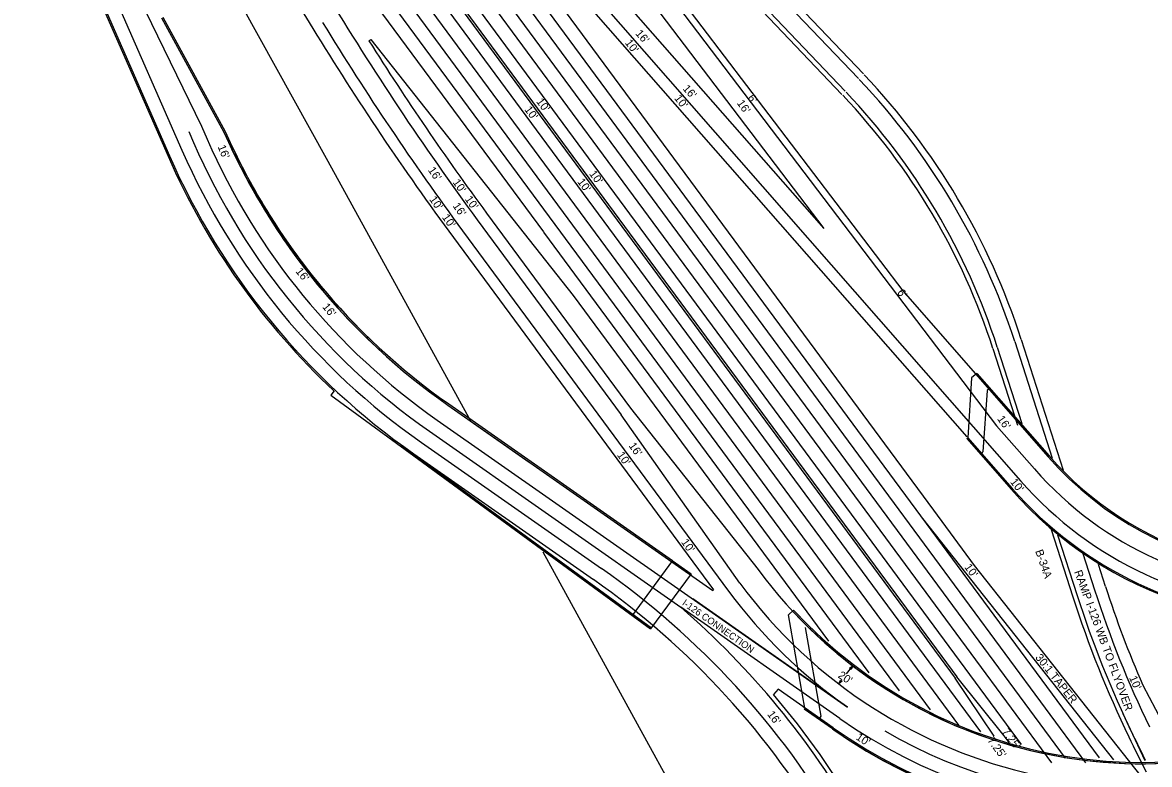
# Model space of a CAD drawing. Extents: x -5665 to 1997148, y 4 to 812485.
# Drawn here: x 1970231 to 1971217, y 796097 to 796747 of the extents above; entities that cross this region are included whole.
import ezdxf

# ---------------------------------------------------------------- set-up
doc = ezdxf.new("R2010")
doc.units = 0
for name, color, linetype in [('BR_CONCRETE', 7, 'Continuous'), ('RD_EX_RailRoad', 7, 'Continuous'), ('RD_PD_ALT1_TrvlWay', 7, 'Continuous'), ('RD_PD_Final_LnLine', 7, 'Continuous'), ('RD_PD_FOC', 7, 'Continuous'), ('RD_PD_MedBWall', 7, 'Continuous'), ('RD_PD_PaveShd', 7, 'Continuous'), ('RD_SHT_TX', 7, 'Continuous')]:
    doc.layers.add(name, color=color, linetype=linetype)

msp = doc.modelspace()

# ---------------------------------------------------------------- linework, layer by layer
at = {"layer": 'BR_CONCRETE'}
for p, q in [((1970278.85, 796811.38), (1970358.4, 796629.63)), ((1970280.04, 796811.9), (1970359.59, 796630.15)), ((1970352.74, 796750.86), (1970407.29, 796650.86)), ((1970353.88, 796751.48), (1970408.44, 796651.48)), ((1971061.08, 796435.65), (1971057.61, 796383.26)), ((1971065.6, 796439.6), (1971061.08, 796435.65)), ((1971064.75, 796438.86), (1971128.01, 796366.63)), ((1971065.6, 796439.6), (1971128.86, 796367.37)), ((1970503.59, 796424.4), (1970500.86, 796420.68)), ((1971074.53, 796424.66), (1971070.98, 796371.04)), ((1971076.88, 796426.72), (1971074.53, 796424.66)), ((1970500.86, 796420.68), (1970780.35, 796216.05)), ((1970603.04, 796411.88), (1970834.74, 796249.56)), ((1970603.79, 796412.95), (1970799.42, 796275.9)), ((1970562.6, 796376.87), (1970781.01, 796216.96)), ((1971056.77, 796382.52), (1971057.61, 796383.26)), ((1971056.77, 796382.52), (1971095.57, 796338.22)), ((1971057.71, 796383.15), (1971096.42, 796338.96)), ((1971068.63, 796368.98), (1971070.98, 796371.04)), ((1970799.42, 796275.9), (1970764.24, 796227.85)), ((1970799.34, 796275.79), (1970815.7, 796264.33)), ((1970815.7, 796264.33), (1970780.35, 796216.05)), ((1970905.37, 796232.3), (1970900.97, 796228.22)), ((1970915.33, 796146.71), (1970900.97, 796228.22)), ((1970929.42, 796139.56), (1970915.76, 796217.11)), ((1970939.35, 796128.51), (1970914.68, 796145.79)), ((1970927.41, 796136.87), (1970929.42, 796139.56))]:
    msp.add_line(p, q, dxfattribs=at)
for centre, radius, start, end in [((1970931.23, 796880.36), 572, 203.65523, 234.98689), ((1970931.23, 796880.36), 570.7, 203.65523, 226.21747), ((1970931.23, 796880.36), 570.7, 203.65523, 234.98689), ((1970931.23, 796880.36), 572, 204.69023, 226.09408), ((1970931.23, 796880.36), 625.3, 203.63926, 226.83775), ((1970931.23, 796880.36), 624, 203.63926, 234.98689), ((1971352.19, 796562.97), 296.88, 221.21202, 283.84721), ((1971352.19, 796562.97), 341.12, 221.21202, 283.34585), ((1971352.19, 796562.97), 340, 221.21202, 314.87827), ((1971210.82, 796516.01), 418, 222.88665, 298.92325), ((1971210.82, 796516.01), 416.88, 222.88665, 298.92325), ((1971210.82, 796516.01), 473.13, 234.98689, 298.92325), ((1971210.82, 796516.01), 472, 234.98689, 298.92325), ((1971210.82, 796516.01), 473.3, 235.20921, 298.92325)]:
    msp.add_arc(centre, radius, start, end, dxfattribs=at)
at = {"layer": 'RD_EX_RailRoad'}
for points in [[(1970394.16, 796813.47), (1970496.54, 796627.92), (1970507.6, 796607.79), (1970622.93, 796398.12)], [(1970685.98, 796283.41), (1970768.64, 796132.97), (1970840.22, 796002.22)]]:
    msp.add_lwpolyline(points, dxfattribs=at)
at = {"layer": 'RD_PD_ALT1_TrvlWay'}
for p, q in [((1970231.16, 797299.2), (1971104.27, 796114.85)), ((1970295.08, 797293.39), (1971172.59, 796103.07)), ((1970542.11, 797011.33), (1970931.78, 796566.41)), ((1970530.07, 797000.79), (1971103.94, 796345.55)), ((1970477.72, 796927.67), (1971068.8, 796125.89)), ((1970439.11, 796899.16), (1970686.58, 796563.47)), ((1970962.1, 796697.61), (1970802.6, 796865.16)), ((1970294.05, 796849.07), (1970387.55, 796656.07)), ((1970950.51, 796686.58), (1970791.01, 796854.13)), ((1970291.03, 796816.71), (1970370.59, 796634.96)), ((1970763.61, 796814.32), (1971082.9, 796393.86)), ((1970750.87, 796804.64), (1970931.78, 796566.41)), ((1970387.55, 796656.07), (1970392.57, 796644.59)), ((1970628.84, 796574.04), (1970754.67, 796403.36)), ((1970615.97, 796564.55), (1970848.6, 796248.98)), ((1970686.68, 796563.34), (1970971.08, 796177.55)), ((1971098.74, 796467.52), (1971131.52, 796365.52)), ((1971083.51, 796462.62), (1971105.02, 796395.7)), ((1970593.86, 796398.78), (1970952.62, 796147.45)), ((1970858.26, 796256.1), (1970754.67, 796403.36)), ((1971082.9, 796393.86), (1971115.97, 796356.09)), ((1970580.09, 796379.12), (1970737.35, 796268.95)), ((1971018.07, 796312.68), (1971185.03, 796101.32)), ((1971136.3, 796298.37), (1971153.36, 796245.28)), ((1971158.37, 796281.99), (1971168.6, 796250.18)), ((1970952.62, 796147.45), (1970817.21, 796242.31)), ((1970945.74, 796137.62), (1970806.83, 796234.93)), ((1971193.35, 796142), (1971212.61, 796100.82))]:
    msp.add_line(p, q, dxfattribs=at)
for centre, radius, start, end in [((1972641.14, 798057.51), 2500, 210.91274, 216.39766), ((1972641.14, 798057.51), 2516, 211.39766, 216.39766), ((1970527.52, 796283.91), 600, 17.81866, 43.48334), ((1970527.52, 796283.91), 584, 17.81866, 43.48334), ((1970931.23, 796880.36), 588, 203.63926, 234.98689), ((1970931.23, 796880.36), 612, 203.63926, 234.98689), ((1971352.19, 796562.97), 314, 221.21202, 318.86296), ((1971352.19, 796562.97), 330, 221.21202, 316.81039), ((1970326.54, 795682.53), 716, 29.92814, 54.98689), ((1971210.82, 796516.01), 438, 216.39766, 298.92325), ((1971210.82, 796516.01), 450, 216.39766, 234.98689), ((1972056.84, 796535.68), 933, 197.81866, 205.76109), ((1972056.84, 796535.68), 949, 197.81866, 205.76109), ((1970326.54, 795682.53), 732, 29.92814, 48.99436), ((1971210.82, 796516.01), 462, 234.98689, 298.92325), ((1972855.69, 796921.19), 1836, 205.76109, 206.51765)]:
    msp.add_arc(centre, radius, start, end, dxfattribs=at)
at = {"layer": 'RD_PD_Final_LnLine'}
for p, q in [((1970260.14, 797320.57), (1971160.74, 796098.91)), ((1970250.48, 797313.45), (1971142.93, 796102.85)), ((1970240.82, 797306.32), (1971130.94, 796098.89)), ((1970468.06, 796920.55), (1971049.57, 796131.75)), ((1970448.75, 796906.31), (1970838.13, 796378.12)), ((1970458.41, 796913.43), (1971024.81, 796145.12)), ((1970586.97, 796388.95), (1970806.83, 796234.93)), ((1970838.13, 796378.12), (1970997.61, 796161.78))]:
    msp.add_line(p, q, dxfattribs=at)
for centre, radius, start, end in [((1970931.23, 796880.36), 600, 202.42407, 234.98689), ((1971210.82, 796516.01), 450, 239.88793, 298.92325)]:
    msp.add_arc(centre, radius, start, end, dxfattribs=at)
at = {"layer": 'RD_PD_FOC'}
msp.add_arc((1971352.19, 796562.97), 298, 221.21202, 301.34068, dxfattribs=at)
msp.add_arc((1971352.19, 796562.97), 298, 221.21202, 301.34068, dxfattribs=at)
at = {"layer": 'RD_PD_MedBWall'}
for p, q in [((1970485.77, 796933.61), (1971046.58, 796172.88)), ((1970487.38, 796934.79), (1971048.19, 796174.06)), ((1971080.89, 796122.04), (1971046.58, 796172.88)), ((1971089.57, 796122.57), (1971048.19, 796174.06))]:
    msp.add_line(p, q, dxfattribs=at)
at = {"layer": 'RD_PD_PaveShd'}
for p, q in [((1970487.38, 796934.79), (1971048.19, 796174.06)), ((1970377.42, 796917.81), (1970485.02, 796741.53)), ((1970966.44, 796701.75), (1970806.94, 796869.3)), ((1970947.61, 796683.82), (1970788.11, 796851.37)), ((1970664.28, 796832.37), (1971056.79, 796384.21)), ((1970768.39, 796817.95), (1971000.85, 796511.82)), ((1970691.5, 796775.88), (1971027.63, 796319.93)), ((1970534.02, 796730.8), (1970535.72, 796731.87)), ((1970535.72, 796731.87), (1970712.68, 796507.84)), ((1970636.89, 796579.98), (1970762.72, 796409.3)), ((1970607.92, 796558.62), (1970835.24, 796250.26)), ((1970712.68, 796507.84), (1970935.77, 796205.23)), ((1971000.85, 796511.82), (1971128.01, 796366.63)), ((1971000.85, 796511.82), (1971128.01, 796366.63)), ((1971104.45, 796469.35), (1971141.21, 796354.98)), ((1971079.7, 796461.4), (1971101.27, 796394.29)), ((1970603.04, 796411.88), (1970674.13, 796362.08)), ((1970762.72, 796409.3), (1970874.36, 796267.97)), ((1970573.2, 796369.29), (1970730.47, 796259.12)), ((1971027.63, 796319.93), (1971063.23, 796271.64)), ((1971130.64, 796302.92), (1971149.56, 796244.06)), ((1971063.23, 796271.64), (1971208.88, 796087.26)), ((1971178.12, 796253.24), (1971171.97, 796272.37)), ((1970835.24, 796250.26), (1970834.77, 796249.6)), ((1970891.81, 796163.19), (1970887.74, 796158.71)), ((1970940, 796129.43), (1970891.81, 796163.19)), ((1971210.72, 796166.89), (1971227.37, 796135.4)), ((1970940, 796129.43), (1970914.46, 796147.32)), ((1971093.91, 796116.68), (1971089.57, 796122.57))]:
    msp.add_line(p, q, dxfattribs=at)
for centre, radius, start, end in [((1972641.14, 798057.51), 2526, 211.39766, 216.39766), ((1972641.14, 798057.51), 2490, 212.19585, 216.39766), ((1970527.52, 796283.91), 606, 17.81866, 43.48334), ((1970527.52, 796283.91), 580, 17.81866, 43.48334), ((1970931.23, 796880.36), 572, 203.65523, 234.98689), ((1970931.23, 796880.36), 572, 203.65523, 234.98689), ((1971210.82, 796516.01), 418, 216.39766, 298.92325), ((1971210.82, 796516.01), 418, 216.39766, 298.92325), ((1970326.54, 795682.53), 704, 29.92814, 54.98689), ((1972056.84, 796535.68), 923, 197.81866, 203.55032), ((1972056.84, 796535.68), 953, 197.81866, 205.76109), ((1970326.54, 795682.53), 736, 29.92814, 40.31481), ((1971210.82, 796516.01), 472, 234.98689, 298.92325), ((1971210.82, 796516.01), 472, 234.98689, 298.92325), ((1972855.69, 796921.19), 1840, 205.76109, 206.82633)]:
    msp.add_arc(centre, radius, start, end, dxfattribs=at)
at = {"layer": 'RD_SHT_TX'}
for p, q in [((1970951.62, 796176.58), (1970957.13, 796183.79)), ((1970957.13, 796183.79), (1970956.18, 796182.55)), ((1970944.99, 796167.9), (1970947.37, 796171.02)), ((1970944.99, 796167.9), (1970946.47, 796169.84))]:
    msp.add_line(p, q, dxfattribs=at)
for points in [[(1970954.31, 796181.54), (1970957.13, 796183.79), (1970955.7, 796180.48)], [(1970947.81, 796170.15), (1970944.99, 796167.9), (1970946.42, 796171.21)]]:
    msp.add_lwpolyline(points, close=True, dxfattribs=at)

# ---------------------------------------------------------------- texts
for s, height, rotation, p in [("16'", 7, 310.55492, (1970766.66, 796736.86)), ("10'", 7, 307.53142, (1970757.56, 796728.85)), ("16'", 7, 311.65276, (1970807.99, 796688.57)), ("10'", 7, 306.39925, (1970680.01, 796677.48)), ("10'", 7, 307.53142, (1970800.66, 796680.38)), ("6'", 7, 305.3319, (1970864.79, 796680.79)), ("10'", 7, 306.39925, (1970669.65, 796670.51)), ("16'", 7, 305.3319, (1970855.47, 796676.14)), ("16'", 7, 292.04214, (1970401.67, 796638.07)), ("16'", 7, 304.83624, (1970585.36, 796617.48)), ("10'", 7, 306.39925, (1970726.3, 796614.22)), ("10'", 7, 304.83624, (1970607, 796606.85)), ("10'", 7, 306.39925, (1970715.94, 796607.25)), ("10'", 7, 304.83624, (1970586.51, 796591.96)), ("10'", 7, 304.83624, (1970617.62, 796592.13)), ("16'", 7, 304.83624, (1970606.97, 796586.23)), ("10'", 7, 304.83624, (1970597.63, 796576.24)), ("16'", 7, 308.77906, (1970469.49, 796528.81)), ("6'", 7, 305.3319, (1970995.55, 796510.42)), ("16'", 7, 308.77906, (1970492.88, 796497.76)), ("16'", 7, 305.3319, (1971083.1, 796399.76)), ("16'", 7, 304.83624, (1970760.86, 796376.33)), ("10'", 7, 304.83624, (1970750.68, 796368.23)), ("10'", 7, 307.53142, (1971094.39, 796344.53)), ("10'", 7, 304.83624, (1970806.77, 796291.94)), ('B-34A', 7, 289.1995, (1971116.57, 796284.11)), ("10'", 7, 306.39925, (1971054.37, 796270)), ('RAMP I-126 WB TO FLYOVER', 7, 290.25504, (1971150.62, 796266)), ('I-126 CONNECTION', 5.9996, 324.94106, (1970807.39, 796237.4)), ('30:1 TAPER', 7, 308.30681, (1971116.34, 796190.87)), ("20'", 7, 326.14848, (1970943.62, 796173.89)), ("10'", 7, 293.24157, (1971198.66, 796173.29)), ("16'", 7, 306.13815, (1970882.01, 796141.24)), ("7.25'", 7, 306.26384, (1971087.15, 796126.01)), ("10'", 7, 326.14848, (1970959.28, 796119.82)), ("7.25'", 7, 306.26384, (1971074.51, 796118.32))]:
    msp.add_text(s, height=height, rotation=rotation, dxfattribs=at).set_placement(p)

doc.saveas('drawing.dxf')
